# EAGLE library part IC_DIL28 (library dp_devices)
universal DIP-28
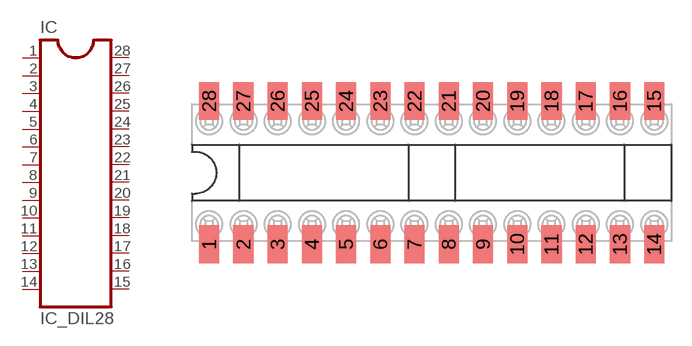
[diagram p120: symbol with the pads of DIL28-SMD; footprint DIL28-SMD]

Designator prefix IC

## IC_DIL28-DIL28-SMD  [DIL28-SMD]
1  1
2  2
3  3
4  4
5  5
6  6
7  7
8  8
9  9
10  10
11  11
12  12
13  13
14  14
15  15
16  16
17  17
18  18
19  19
20  20
21  21
22  22
23  23
24  24
25  25
26  26
27  27
28  28

## Footprint DIL28-SMD (pad centres in mm)
0.1" pitch 28 DIP socket to SMD Mfr no: SHD-028-3 SHD-028-3
smd 1.5 x 2.8: 1 -16.51,-5.31; 2 -13.97,-5.31; 3 -11.43,-5.31; 4 -8.89,-5.31; 5 -6.35,-5.31; 6 -3.81,-5.31; 7 -1.27,-5.31; 8 1.27,-5.31; 9 3.81,-5.31; 10 6.35,-5.31; 11 8.89,-5.31; 12 11.43,-5.31; 13 13.97,-5.31; 14 16.51,-5.31; 15 16.51,5.31; 16 13.97,5.31; 17 11.43,5.31; 18 8.89,5.31; 19 6.35,5.31; 20 3.81,5.31; 21 1.27,5.31; 22 -1.27,5.31; 23 -3.81,5.31; 24 -6.35,5.31; 25 -8.89,5.31; 26 -11.43,5.31; 27 -13.97,5.31; 28 -16.51,5.31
